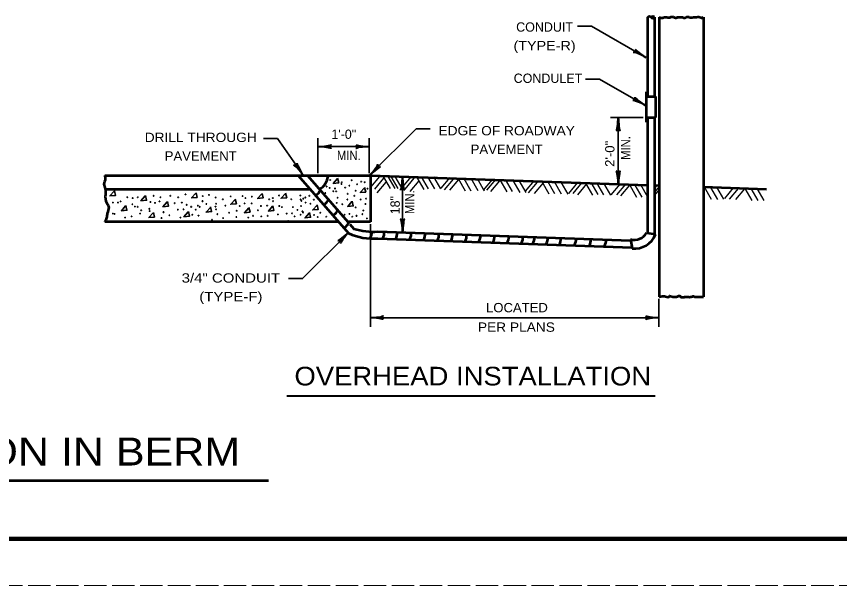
# Model space of a CAD drawing. Extents: x -58 to 622, y -372 to 68.
# Drawn here: x 200.3 to 376.8, y -372 to -249.9 of the extents above; entities that cross this region are included whole.
import ezdxf
from ezdxf.enums import TextEntityAlignment as Align

# ---------------------------------------------------------------- set-up
doc = ezdxf.new("R2010")
doc.units = 0
doc.header["$LTSCALE"] = 0.8
doc.linetypes.add('LONG_DASHED', pattern=[7.5, 6, -1.5])
doc.layers.add('1', color=7, linetype='Continuous', lineweight=35)
doc.layers.add('61', color=7, linetype='Continuous', lineweight=35)

msp = doc.modelspace()

# ---------------------------------------------------------------- linework, layer by layer
at = {"layer": '1', "lineweight": 53}
for p, q in [((335.6542, -250.0603), (335.6542, -267.0735)), ((337.1542, -250.0603), (337.1542, -267.0444)), ((338.1542, -250.0603), (338.1542, -310.0603)), ((347.6542, -250.0603), (347.6542, -310.0603)), ((335.3657, -266.0735), (335.3657, -272.5735)), ((335.3657, -267.0735), (337.3657, -267.0735)), ((337.3657, -267.0735), (337.3657, -271.5735)), ((335.3657, -271.5735), (336.1215, -271.5735)), ((335.6542, -271.6081), (335.6542, -296.3446)), ((260.7029, -283.9838), (271.5212, -296.4288)), ((262.6904, -283.9838), (271.3629, -293.9603)), ((276.1904, -283.9838), (335.6577, -286.0605)), ((219.1904, -286.9838), (263.3107, -286.9838)), ((337.1684, -286.1132), (338.1427, -286.1472)), ((347.6183, -286.4781), (361.1402, -286.9502)), ((269.264, -293.9838), (219.1904, -293.9838)), ((276.1904, -293.9838), (271.3599, -293.9838)), ((271.8045, -294.4684), (272.6533, -295.4447)), ((277.8081, -296.0476), (332.0119, -297.9405)), ((335.4013, -296.3), (337.3707, -296.6472)), ((277.7557, -297.5467), (332.2782, -299.4507)), ((331.9733, -297.7213), (332.3205, -299.6909)), ((122.0016, -349.4891), (254.329, -349.4891))]:
    msp.add_line(p, q, dxfattribs=at)
at = {"layer": '1'}
for p, q in [((334.7117, -271.5813), (327.7117, -271.5813)), ((329.3632, -271.5813), (329.3632, -285.9298)), ((264.9297, -283.5143), (264.9297, -276.0143)), ((275.9297, -283.5143), (275.9297, -276.0143)), ((264.9297, -277.8252), (275.9297, -277.8252)), ((283.0888, -284.2984), (283.0888, -296.1737)), ((276.1878, -294.4728), (276.1878, -316.4728)), ((338.0836, -310.4742), (338.0836, -316.4728)), ((276.1108, -314.5437), (338.084, -314.5437))]:
    msp.add_line(p, q, dxfattribs=at)
at = {"layer": '1', "lineweight": 25}
for p, q in [((278.1212, -284.214), (276.1928, -286.5123)), ((278.9219, -284.201), (280.4219, -286.7991)), ((279.8952, -284.201), (281.3952, -286.7991)), ((280.5441, -284.201), (282.0441, -286.7991)), ((281.4362, -284.201), (282.9362, -286.7991)), ((284.9343, -284.214), (283.006, -286.5123)), ((279.0133, -284.6195), (277.085, -286.9178)), ((279.5, -285.4306), (277.5717, -287.7289)), ((285.5021, -284.6195), (283.5738, -286.9178)), ((286.5565, -285.1873), (284.6282, -287.4856)), ((286.1406, -284.4443), (287.6406, -287.0424)), ((287.1139, -284.2821), (288.6139, -286.8802)), ((288.4117, -284.2821), (289.9117, -286.8802)), ((289.7094, -284.2821), (291.2094, -286.8802)), ((293.2074, -284.4573), (291.2791, -286.7557)), ((293.9374, -284.7817), (292.0091, -287.0801)), ((295.0729, -284.8628), (293.1446, -287.1612)), ((294.9815, -284.6877), (296.4815, -287.2858)), ((296.1982, -284.6877), (297.6982, -287.2858)), ((297.7392, -284.6065), (299.2392, -287.2046)), ((299.1181, -284.6877), (300.6181, -287.2858)), ((302.2917, -284.8628), (300.3633, -287.1612)), ((303.0217, -284.8628), (301.0933, -287.1612)), ((303.9138, -285.1873), (301.9855, -287.4856)), ((303.9846, -284.9309), (305.4846, -287.529)), ((305.1202, -284.8498), (306.6202, -287.4479)), ((306.7423, -285.0932), (308.2423, -287.6912)), ((308.0401, -285.0932), (309.5401, -287.6912)), ((311.2947, -285.1062), (309.3664, -287.4045)), ((311.9437, -285.4306), (310.0153, -287.7289)), ((313.2414, -285.5928), (311.3131, -287.8912)), ((312.9878, -285.3365), (314.4878, -287.9346)), ((314.2043, -285.2554), (315.7043, -287.8535)), ((315.5832, -285.3365), (317.0832, -287.9346)), ((317.0432, -285.4176), (318.5432, -288.0157)), ((320.5817, -285.5523), (318.6534, -287.8506)), ((321.5145, -285.5523), (319.5862, -287.8506)), ((322.5283, -285.8362), (320.6, -288.1345)), ((322.3152, -285.6609), (323.8152, -288.259)), ((323.4507, -285.4987), (324.9507, -288.0968)), ((324.6674, -285.5798), (326.1674, -288.1779)), ((326.2085, -285.6609), (327.7085, -288.259)), ((329.7065, -285.8767), (327.7782, -288.175)), ((330.8826, -285.8767), (328.9543, -288.175)), ((334.1572, -285.9854), (335.6572, -288.5835)), ((331.7748, -286.0795), (329.8465, -288.3778)), ((331.805, -286.0665), (333.305, -288.6646)), ((332.9406, -286.0665), (334.4406, -288.6646)), ((337.7128, -286.1322), (337.1542, -286.7982)), ((338.1542, -286.4056), (337.1542, -287.5974)), ((338.1542, -287.0597), (337.1542, -288.2515)), ((347.7923, -286.4734), (349.2923, -289.0715)), ((349.1294, -286.5897), (350.6294, -289.1877)), ((350.4084, -286.5316), (351.9084, -289.1297)), ((354.0408, -286.6608), (352.1125, -288.9592)), ((355.0872, -286.8352), (353.1589, -289.1336)), ((356.4243, -286.8934), (354.496, -289.1918)), ((356.5127, -286.8222), (358.0127, -289.4203)), ((357.7917, -286.8222), (359.2917, -289.4203)), ((359.0707, -286.8222), (360.5707, -289.4203))]:
    msp.add_line(p, q, dxfattribs=at)
at = {"layer": '1', "lineweight": 40}
msp.add_line((258.2395, -331.2874), (337.3024, -331.2874), dxfattribs=at)
at = {"layer": '1'}
for points in [[(335.2931, -258.6751), (323.6017, -251.9251), (320.6017, -251.9251)], [(335.1887, -269.0025), (325.3458, -263.3197), (322.3458, -263.3197)], [(276.0824, -283.9095), (285.9819, -274.01), (288.9819, -274.01)], [(261.7322, -283.9311), (256.2447, -276.094), (253.2447, -276.094)], [(269.1261, -284.694), (268.2047, -285.7305), (269.3947, -285.6153), (269.1644, -284.6173)], [(221.2519, -287.3774), (220.3306, -288.4139), (221.5206, -288.2987), (221.2902, -287.3007)], [(238.755, -287.8043), (237.8337, -288.8408), (239.0237, -288.7257), (238.7933, -287.7276)], [(274.9197, -286.6456), (273.9984, -287.6821), (275.1884, -287.5669), (274.9581, -286.5688)], [(227.8994, -288.4142), (226.9781, -289.4507), (228.1681, -289.3355), (227.9377, -288.3374)], [(247.1711, -289.146), (246.2498, -290.1825), (247.4398, -290.0673), (247.2094, -289.0693)], [(252.9038, -287.9262), (251.9824, -288.9627), (253.1724, -288.8476), (252.9421, -287.8495)], [(257.9656, -287.8653), (257.0442, -288.9018), (258.2342, -288.7867), (258.0039, -287.7886)], [(223.6914, -290.5487), (222.7701, -291.5852), (223.9601, -291.47), (223.7297, -290.4719)], [(232.5953, -289.6949), (231.674, -290.7314), (232.864, -290.6162), (232.6337, -289.6182)], [(241.8653, -290.8536), (240.9439, -291.8901), (242.1339, -291.7749), (241.9036, -290.7768)], [(250.0984, -290.9756), (249.1771, -292.0121), (250.3671, -291.8969), (250.1367, -290.8988)], [(255.2212, -290.6097), (254.2999, -291.6462), (255.4899, -291.531), (255.2596, -290.5329)], [(264.7351, -290.3657), (263.8137, -291.4022), (265.0037, -291.2871), (264.7734, -290.289)], [(272.2363, -289.6339), (271.315, -290.6704), (272.505, -290.5553), (272.2747, -289.5572)], [(229.607, -292.0123), (228.6857, -293.0488), (229.8757, -292.9337), (229.6453, -291.9356)], [(237.1083, -291.8294), (236.187, -292.8659), (237.377, -292.7507), (237.1467, -291.7527)], [(263.0884, -292.0733), (262.1671, -293.1098), (263.3571, -292.9947), (263.1268, -291.9966)], [(271.5311, -296.2456), (261.6316, -306.1451), (258.6316, -306.1451)]]:
    msp.add_lwpolyline(points, dxfattribs=at)
at = {"layer": '1', "lineweight": 53}
for points in [[(336.1215, -271.5735), (337.1098, -271.5735), (337.3657, -271.5735)], [(337.1542, -271.6081), (337.1542, -286.1272), (337.1542, -296.6091)], [(219.1904, -283.9838), (276.1904, -283.9838), (276.1904, -293.9838)]]:
    msp.add_lwpolyline(points, dxfattribs=at)
at = {"layer": '1'}
for centre in [(267.5679, -284.9851), (269.9925, -285.8338), (270.0532, -285.47), (272.1747, -285.0457), (273.3264, -285.8943), (274.2357, -285.3487), (274.963, -285.47), (266.5374, -287.7734), (266.7799, -286.3793), (267.4467, -286.6823), (268.2347, -287.4097), (268.5983, -286.8036), (268.8408, -287.4097), (270.7805, -286.6217), (271.6898, -286.1974), (273.0233, -287.2885), (275.5692, -286.8642), (222.591, -289.5919), (224.0457, -288.6827), (225.1975, -288.8645), (226.2886, -288.6827), (229.6831, -288.3796), (230.956, -289.5919), (231.1378, -288.6827), (233.2594, -288.3796), (234.9566, -288.6827), (236.5327, -288.0765), (240.1696, -289.5312), (240.2302, -288.4402), (241.5637, -288.1977), (243.0185, -288.7432), (244.5339, -289.107), (246.2312, -288.5008), (248.777, -288.4402), (249.3832, -288.8645), (250.7773, -288.5614), (254.4749, -289.107), (255.2629, -288.8645), (255.3235, -289.5312), (256.5964, -288.3189), (259.2029, -289.107), (261.1427, -288.3189), (261.2032, -289.1676), (261.3851, -289.4707), (261.8094, -288.9857), (262.2337, -288.7432), (263.0823, -288.3796), (264.0522, -289.2282), (269.1439, -288.8039), (271.2654, -289.1676), (271.3261, -287.9552), (272.7202, -288.3796), (274.1144, -289.1676), (275.2661, -288.9857), (220.9544, -289.8343), (222.0455, -289.8343), (225.1368, -290.1981), (225.6824, -290.683), (226.2886, -290.7436), (228.7738, -291.1679), (229.0162, -289.7131), (229.9862, -289.895), (234.2292, -289.9556), (234.896, -291.3497), (235.7447, -289.8343), (236.1083, -291.2892), (236.7751, -290.3193), (237.7449, -290.7436), (238.7148, -291.3497), (239.1997, -290.5011), (239.5634, -290.7436), (241.0182, -290.1374), (242.9579, -290.683), (243.0792, -290.0768), (243.0792, -291.2892), (245.0794, -290.5011), (248.1708, -290.5618), (249.2013, -290.0162), (250.7167, -290.0162), (252.717, -290.5618), (254.0506, -290.5011), (256.6571, -290.5618), (257.2026, -290.8042), (259.5666, -290.8042), (261.3245, -290.5618), (262.2943, -289.8343), (263.3248, -290.0768), (266.9617, -291.1679), (268.9621, -289.895), (270.1743, -290.1981), (273.0233, -290.8648), (275.1448, -290.1374), (220.9544, -292.1983), (221.3181, -292.259), (223.5608, -293.047), (224.955, -292.8045), (226.7735, -292.1983), (227.016, -291.471), (228.8344, -291.6528), (231.8046, -291.8952), (233.0775, -292.5621), (235.4416, -293.047), (237.9874, -292.4408), (239.3209, -292.6227), (243.3822, -292.3196), (245.8674, -292.0165), (247.4435, -292.9257), (247.5041, -291.5922), (249.9893, -293.047), (251.0198, -292.6832), (252.0503, -291.471), (252.7777, -292.8045), (254.1718, -292.6832), (256.354, -292.3802), (258.2331, -292.1983), (259.3847, -292.1377), (259.9303, -292.8045), (260.5365, -291.4103), (261.2032, -292.4408), (261.6276, -291.7134), (261.7487, -291.9559), (264.1128, -292.5014), (264.9008, -292.9257), (265.4463, -292.0165), (266.7192, -292.8652), (270.6593, -292.4408), (271.6898, -292.259), (272.2959, -292.8652), (273.2052, -292.6832), (274.4781, -292.3196), (274.6599, -291.5316), (231.3803, -293.1683), (242.2305, -293.5319), (244.5945, -293.1683), (258.5362, -293.7743), (275.4479, -293.2288)]:
    msp.add_circle(centre, 0.0607, dxfattribs=at)
at = {"layer": '1', "lineweight": 53}
for centre, radius, start, end in [((336.0292, -250.4071), 0.4965, 40.95184, 139.04816), ((336.7735, -249.732), 0.4984, 221.20556, 318.79444), ((336.7792, -250.4273), 0.5247, 44.37838, 135.62162), ((263.3525, -283.756), 3.7689, 301.08152, 353.13064), ((263.4115, -286.3695), 2.1707, 299.00343, 339.84739), ((265.208, -288.3457), 2.1707, 299.00343, 339.84739), ((267.1841, -290.6213), 2.1707, 299.00343, 339.84739), ((269.5196, -293.3759), 2.1707, 299.00343, 339.84739), ((276.8528, -284.6377), 12.9405, 245.66897, 274.00127), ((276.7774, -282.5203), 13.5665, 252.30241, 274.35724), ((274.296, -296.3416), 2.1707, 327.00343, 7.84739), ((276.9908, -296.3416), 2.1707, 327.00343, 7.84739), ((279.7753, -296.4913), 2.1707, 327.00343, 7.84739), ((282.7995, -296.5212), 2.1707, 327.00343, 7.84739), ((285.7638, -296.641), 2.1707, 327.00343, 7.84739), ((288.728, -296.7608), 2.1707, 327.00343, 7.84739), ((291.6324, -296.8506), 2.1707, 327.00343, 7.84739), ((332.8255, -294.9323), 2.9163, 253.00765, 332.03255), ((294.6565, -297.0004), 2.1707, 327.00343, 7.84739), ((297.6208, -297.0902), 2.1707, 327.00343, 7.84739), ((300.6449, -297.18), 2.1707, 327.00343, 7.84739), ((303.699, -297.3297), 2.1707, 327.00343, 7.84739), ((306.7531, -297.3297), 2.1707, 327.00343, 7.84739), ((309.2083, -297.5094), 2.1707, 327.00343, 7.84739), ((312.0528, -297.5992), 2.1707, 327.00343, 7.84739), ((314.8673, -297.689), 2.1707, 327.00343, 7.84739), ((318.131, -297.8088), 2.1707, 327.00343, 7.84739), ((321.3048, -297.9285), 2.1707, 327.00343, 7.84739), ((324.5685, -298.0184), 2.1707, 327.00343, 7.84739), ((332.8325, -294.8288), 4.889, 263.98872, 338.16404)]:
    msp.add_arc(centre, radius, start, end, dxfattribs=at)
at = {"layer": '1', "lineweight": 40}
for centre, major_axis, ratio, start_param, end_param in [((334.2099, -258.3688), (1.6245, -0.7576), 0.122415, 0.89635335, 3.14159265), ((334.2099, -258.3688), (1.6245, -0.7576), 0.122415, 0.89635335, 3.14159265), ((334.4285, -257.9316), (-1.4333, 1.0303), 0.07063, 6.28230741, 8.55970261), ((334.4285, -257.9316), (-1.4333, 1.0303), 0.07063, 6.28230741, 8.55970261), ((334.1055, -268.6962), (1.6245, -0.7576), 0.122415, 0.89635335, 3.14159265), ((334.1055, -268.6962), (1.6245, -0.7576), 0.122415, 0.89635335, 3.14159265), ((334.3241, -268.259), (1.4333, -1.0303), 0.07063, 3.14071475, 5.41810995), ((334.3241, -268.259), (1.4333, -1.0303), 0.07063, 3.14071475, 5.41810995), ((329.1516, -272.7018), (-0.1757, -1.7565), 0.07063, 6.28230741, 8.55970261), ((329.1516, -272.7018), (-0.1757, -1.7565), 0.07063, 6.28230741, 8.55970261), ((329.6395, -272.6724), (-0.1562, 1.7857), 0.122415, 0.89635335, 3.14159265), ((329.6395, -272.6724), (-0.1562, 1.7857), 0.122415, 0.89635335, 3.14159265), ((266.0502, -278.0369), (1.7565, -0.1757), 0.07063, 6.28230741, 8.55970261), ((266.0502, -278.0369), (1.7565, -0.1757), 0.07063, 6.28230741, 8.55970261), ((266.0209, -277.549), (-1.7857, -0.1562), 0.122415, 0.89635335, 3.14159265), ((266.0209, -277.549), (-1.7857, -0.1562), 0.122415, 0.89635335, 3.14159265), ((274.8385, -278.1015), (1.7857, 0.1562), 0.122415, 0.89635335, 3.14159265), ((274.8385, -278.1015), (1.7857, 0.1562), 0.122415, 0.89635335, 3.14159265), ((274.8092, -277.6136), (1.7565, -0.1757), 0.07063, 3.14071475, 5.41810995), ((274.8092, -277.6136), (1.7565, -0.1757), 0.07063, 3.14071475, 5.41810995), ((260.88, -283.1957), (1.1521, -1.3732), 0.122415, 0.89635335, 3.14159265), ((261.2628, -282.8919), (-0.8636, 1.5396), 0.07063, 6.28230741, 8.55970261), ((276.6586, -282.9425), (-1.1523, -1.3731), 0.122415, 0.89635335, 3.14159265), ((276.6586, -282.9425), (-1.1523, -1.3731), 0.122415, 0.89635335, 3.14159265), ((277.0244, -283.2668), (1.3662, 1.1178), 0.07063, 6.28230741, 8.55970261), ((277.0244, -283.2668), (1.3662, 1.1178), 0.07063, 6.28230741, 8.55970261), ((329.0869, -284.8386), (0.1562, -1.7857), 0.122415, 0.89635335, 3.14159265), ((329.0869, -284.8386), (0.1562, -1.7857), 0.122415, 0.89635335, 3.14159265), ((329.5748, -284.8093), (0.1757, 1.7565), 0.07063, 6.28230741, 8.55970261), ((329.5748, -284.8093), (0.1757, 1.7565), 0.07063, 6.28230741, 8.55970261), ((282.8772, -285.4189), (-0.1757, -1.7565), 0.07063, 6.28230741, 8.55970261), ((282.8772, -285.4189), (-0.1757, -1.7565), 0.07063, 6.28230741, 8.55970261), ((283.3651, -285.3896), (-0.1562, 1.7857), 0.122415, 0.89635335, 3.14159265), ((283.3651, -285.3896), (-0.1562, 1.7857), 0.122415, 0.89635335, 3.14159265), ((282.8125, -295.0826), (0.1562, -1.7857), 0.122415, 0.89635335, 3.14159265), ((282.8125, -295.0826), (0.1562, -1.7857), 0.122415, 0.89635335, 3.14159265), ((283.3004, -295.0532), (0.1757, 1.7565), 0.07063, 6.28230741, 8.55970261), ((283.3004, -295.0532), (0.1757, 1.7565), 0.07063, 6.28230741, 8.55970261), ((270.5891, -296.8883), (1.3662, 1.1178), 0.07063, 3.14071475, 5.41810995), ((270.9549, -297.2126), (1.1523, 1.3731), 0.122415, 0.89635335, 3.14159265), ((277.202, -314.2674), (-1.7857, -0.1562), 0.122415, 0.89635335, 3.14159265), ((336.9635, -314.3321), (1.7565, -0.1757), 0.07063, 3.14071475, 5.41810995), ((277.2313, -314.7553), (1.7565, -0.1757), 0.07063, 6.28230741, 8.55970261), ((336.9928, -314.82), (1.7857, 0.1562), 0.122415, 0.89635335, 3.14159265)]:
    msp.add_ellipse(centre, major_axis=major_axis, ratio=ratio, start_param=start_param, end_param=end_param, dxfattribs=at)
at = {"layer": '1', "lineweight": 53}
for points in [[(338.1542, -250.0603), (338.906, -250.153), (339.2802, -250.0632), (340.0138, -250.0931), (340.4778, -250.0931), (340.6874, -249.9584), (341.2862, -250.0482), (341.9, -250.1231), (342.1396, -250.0182), (342.7533, -250.0332), (343.1874, -250.0182), (343.4419, -250.138), (343.936, -250.0482), (344.0408, -249.9883), (344.4001, -249.9584), (344.5797, -250.0032), (344.924, -250.1231), (345.4779, -250.0632), (345.6576, -250.0032), (345.9569, -250.0182), (346.1542, -250.0603)], [(346.1542, -250.0603), (346.6732, -249.9902), (347.0365, -250.1355), (347.6542, -250.0603)], [(219.1904, -283.9838), (219.3292, -284.7203), (219.0297, -285.8581), (219.3292, -286.8762), (219.3891, -287.6546), (219.4489, -289.511), (220.0477, -290.8284), (219.7483, -292.1458), (219.5687, -293.104), (219.1904, -293.9838)], [(338.1542, -310.0603), (338.7937, -309.956), (339.2428, -309.9111), (340.1859, -310.0757), (340.3656, -309.8812), (340.8446, -310.0159), (341.2338, -310.0608), (341.5931, -310.0608), (341.9374, -310.0608), (342.0572, -309.986), (342.641, -309.9111), (342.7608, -310.1058), (343.0602, -310.1507), (343.5093, -310.1357), (343.7937, -310.0757), (343.9285, -310.0757), (344.2728, -310.0308), (344.662, -310.1058), (345.0063, -310.0458), (345.171, -310.0159), (345.4105, -309.9411), (345.665, -310.0009), (345.9195, -310.0908), (346.1542, -310.0603)], [(346.1542, -310.0603), (346.6877, -310.0365), (347.0947, -310.0656), (347.6542, -310.0603)]]:
    msp.add_spline(points, degree=3, dxfattribs=at)
at = {"layer": '61', "lineweight": 158}
msp.add_line((610.6302, -362.0467), (-28.4297, -362.0267), dxfattribs=at)
at = {"layer": '61', "linetype": 'LONG_DASHED', "lineweight": 13}
msp.add_line((621.5702, -372.0267), (-58.4898, -372.0467), dxfattribs=at)

# ---------------------------------------------------------------- texts
at = {"layer": '1'}
msp.add_text('CONDUIT', height=2, dxfattribs=at).set_placement((313.5504, -253.1405), align=Align.CENTER)
for s, width, p in [('(TYPE-R)', 1.15, (313.5504, -257.1405)), ('EDGE OF ROADWAY', 1.1, (305.4257, -275.3937)), ('DRILL THROUGH', 1.1, (239.7929, -276.8308)), ('PAVEMENT', 1.05, (239.7929, -280.8308)), ('PAVEMENT', 1.05, (305.4257, -279.3937)), ('3/4" CONDUIT', 1.2, (246.2603, -307.0123)), ('(TYPE-F)', 1.2, (246.2604, -311.0123))]:
    msp.add_text(s, height=2, dxfattribs=dict(at, width=width)).set_placement(p, align=Align.CENTER)
for s, p in [('CONDULET', (306.9228, -264.1398)), ('1\'-0"', (267.8185, -276.1541))]:
    msp.add_text(s, height=2, dxfattribs=at).set_placement(p)
for s, width, p in [('2\'-0"', 1.05, (328.5492, -282.162)), ('MIN.', 0.9, (331.9212, -280.6505)), ('MIN.', 0.9, (285.6041, -292.2921))]:
    msp.add_text(s, height=2, rotation=90, dxfattribs=dict(at, width=width)).set_placement(p)
for s, height, width, p in [('MIN.', 2, 0.9, (269.0162, -280.7052)), ('LOCATED', 2, 1.05, (300.9929, -313.3809)), ('PER PLANS', 2, 1.1, (299.2489, -317.5668)), ('OVERHEAD INSTALLATION', 4, 1.1, (259.8941, -329.0888)), ('TYPICAL SECTION IN BERM', 6, 1.15, (125.2095, -346.2812))]:
    msp.add_text(s, height=height, dxfattribs=dict(at, width=width)).set_placement(p)
msp.add_text('18"', height=2, rotation=90, dxfattribs=at).set_placement((282.4903, -292.352))

doc.saveas('drawing.dxf')
